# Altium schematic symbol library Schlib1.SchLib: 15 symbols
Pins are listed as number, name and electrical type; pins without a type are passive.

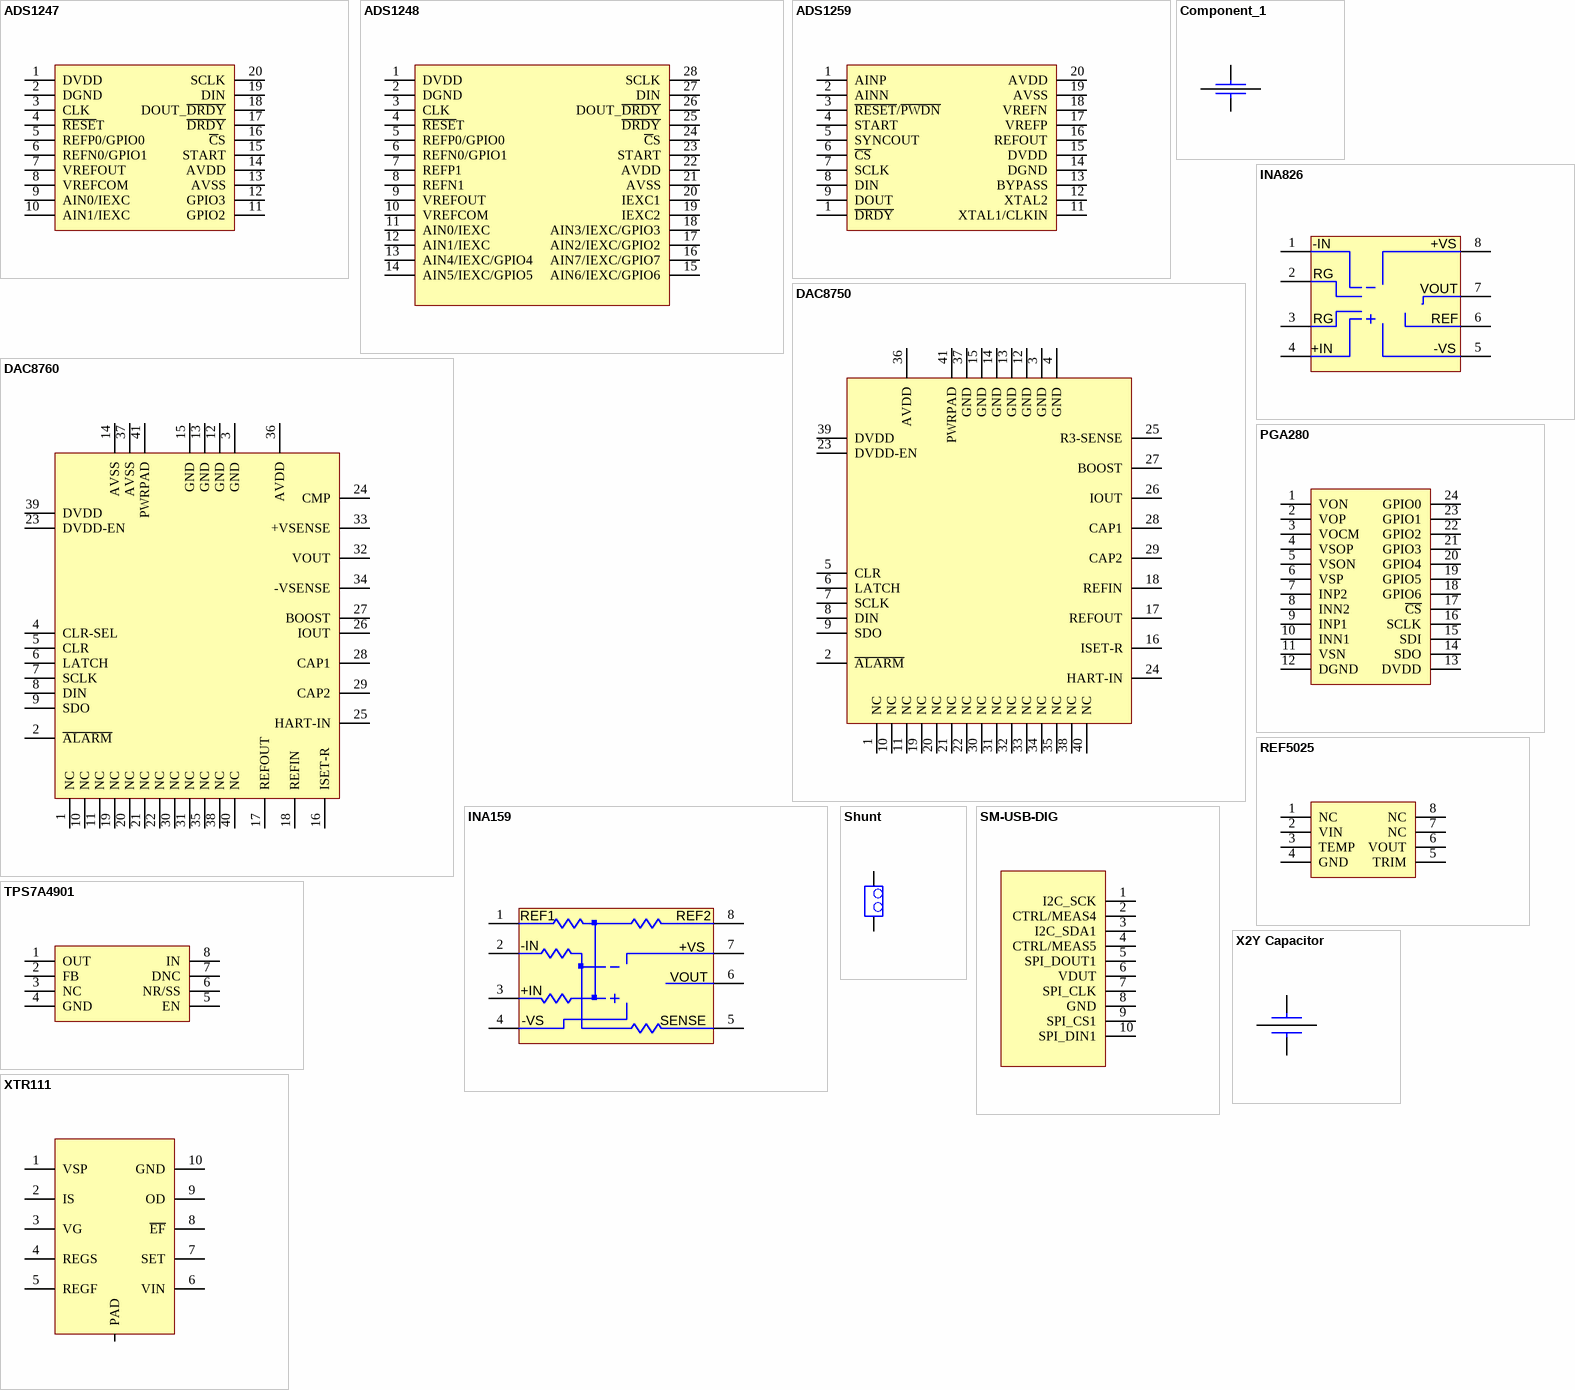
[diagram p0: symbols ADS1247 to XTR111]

## ADS1247
designator U?, comment Used in BOM report
SymbolVersion: use current date i.e. 2008-05-20; SymbolCreator: Use LDAP id; CompType: Used in some BOM reports.  Useful for finding later.; U/M: EA, IN, or GM
pins: 1 DVDD, 2 DGND, 3 CLK, 4 ~{RESE}T, 5 REFP0/GPIO0, 6 REFN0/GPIO1, 7 VREFOUT, 8 VREFCOM, 9 AIN0/IEXC, 10 AIN1/IEXC, 11 GPIO2, 12 GPIO3, 13 AVSS, 14 AVDD, 15 START, 16 ~{C}S, 17 ~{DRDY}, 18 DOUT_~{DRDY}, 19 DIN, 20 SCLK

## ADS1248
designator U?, comment Used in BOM report
SymbolVersion: use current date i.e. 2008-05-20; SymbolCreator: Use LDAP id; CompType: Used in some BOM reports.  Useful for finding later.; U/M: EA, IN, or GM
pins: 1 DVDD, 2 DGND, 3 CLK, 4 ~{RESE}T, 5 REFP0/GPIO0, 6 REFN0/GPIO1, 7 REFP1, 8 REFN1, 9 VREFOUT, 10 VREFCOM, 11 AIN0/IEXC, 12 AIN1/IEXC, 13 AIN4/IEXC/GPIO4, 14 AIN5/IEXC/GPIO5, 15 AIN6/IEXC/GPIO6, 16 AIN7/IEXC/GPIO7, 17 AIN2/IEXC/GPIO2, 18 AIN3/IEXC/GPIO3, 19 IEXC2, 20 IEXC1, 21 AVSS, 22 AVDD, 23 START, 24 ~{C}S, 25 ~{DRDY}, 26 DOUT_~{DRDY}, 27 DIN, 28 SCLK

## ADS1259
designator U?, comment Used in BOM report
SymbolVersion: use current date i.e. 2008-05-20; SymbolCreator: Use LDAP id; CompType: Used in some BOM reports.  Useful for finding later.; U/M: EA, IN, or GM
pins: 1 AINP, 1 ~{DRDY}, 2 AINN, 3 ~{RESET}/~{PWDN}, 4 START, 5 SYNCOUT, 6 ~{CS}, 7 SCLK, 8 DIN, 9 DOUT, 11 XTAL1/CLKIN, 12 XTAL2, 13 BYPASS, 14 DGND, 15 DVDD, 16 REFOUT, 17 VREFP, 18 VREFN, 19 AVSS, 20 AVDD

## Component_1
designator U?, comment Used in BOM report
SymbolVersion: use current date i.e. 2008-05-20; SymbolCreator: Use LDAP id; CompType: Used in some BOM reports.  Useful for finding later.; U/M: EA, IN, or GM
pins: 2, 2, 3, 4

## DAC8750
designator U?, comment Used in BOM report
SymbolVersion: use current date i.e. 2008-05-20; SymbolCreator: Use LDAP id; CompType: Used in some BOM reports.  Useful for finding later.; U/M: EA, IN, or GM
pins: 1 NC, 2 ~{ALARM}, 3 GND, 4 GND, 5 CLR, 6 LATCH, 7 SCLK, 8 DIN, 9 SDO, 10 NC, 11 NC, 12 GND, 13 GND, 14 GND, 15 GND, 16 ISET-R, 17 REFOUT, 18 REFIN, 19 NC, 20 NC, 21 NC, 22 NC, 23 DVDD-EN, 24 HART-IN, 25 R3-SENSE, 26 IOUT, 27 BOOST, 28 CAP1, 29 CAP2, 30 NC, 31 NC, 32 NC, 33 NC, 34 NC, 35 NC, 36 AVDD, 37 GND, 38 NC, 39 DVDD, 40 NC, 41 PWRPAD

## DAC8760
designator U?, comment Used in BOM report
SymbolVersion: use current date i.e. 2008-05-20; SymbolCreator: Use LDAP id; CompType: Used in some BOM reports.  Useful for finding later.; U/M: EA, IN, or GM
pins: 1 NC, 2 ~{ALARM}, 3 GND, 4 CLR-SEL, 5 CLR, 6 LATCH, 7 SCLK, 8 DIN, 9 SDO, 10 NC, 11 NC, 12 GND, 13 GND, 14 AVSS, 15 GND, 16 ISET-R, 17 REFOUT, 18 REFIN, 19 NC, 20 NC, 21 NC, 22 NC, 23 DVDD-EN, 24 CMP, 25 HART-IN, 26 IOUT, 27 BOOST, 28 CAP1, 29 CAP2, 30 NC, 31 NC, 32 VOUT, 33 +VSENSE, 34 -VSENSE, 35 NC, 36 AVDD, 37 AVSS, 38 NC, 39 DVDD, 40 NC, 41 PWRPAD

## INA159
designator U?, comment Used in BOM report
SymbolVersion: use current date i.e. 2008-05-20; SymbolCreator: Use LDAP id; CompType: Used in some BOM reports.  Useful for finding later.; U/M: EA, IN, or GM
pins: 1 REF1, 2 -IN, 3 +IN, 4 V-, 5 SENSE, 6 OUT, 7 VOUT, 8 REF2

## INA826
designator U?, comment Used in BOM report
SymbolVersion: use current date i.e. 2008-05-20; SymbolCreator: Use LDAP id; CompType: Used in some BOM reports.  Useful for finding later.; U/M: EA, IN, or GM
pins: 1 -IN, 2 RG, 3 RG, 4 +IN, 5 -VS, 6 REF, 7 VOUT, 8 +VS

## PGA280
designator U?, comment Used in BOM report
SymbolVersion: use current date i.e. 2008-05-20; SymbolCreator: Use LDAP id; CompType: Used in some BOM reports.  Useful for finding later.; U/M: EA, IN, or GM
pins: 1 VON, 2 VOP, 3 VOCM, 4 VSOP, 5 VSON, 6 VSP, 7 INP2, 8 INN2, 9 INP1, 10 INN1, 11 VSN, 12 DGND, 13 DVDD, 14 SDO, 15 SDI, 16 SCLK, 17 ~{CS}, 18 GPIO6, 19 GPIO5, 20 GPIO4, 21 GPIO3, 22 GPIO2, 23 GPIO1, 24 GPIO0

## REF5025
designator U?, comment Used in BOM report
SymbolVersion: use current date i.e. 2008-05-20; SymbolCreator: Use LDAP id; CompType: Used in some BOM reports.  Useful for finding later.; U/M: EA, IN, or GM
pins: 1 NC, 2 VIN, 3 TEMP, 4 GND, 5 TRIM, 6 VOUT, 7 NC, 8 NC

## Shunt
designator J?, comment Used in BOM report  (value not drawn)
SymbolVersion: use current date i.e. 2008-05-20; SymbolCreator: Use LDAP id; CompType: Used in some BOM reports.  Useful for finding later.; U/M: EA, IN, or GM
pins: 1, 2

## SM-USB-DIG
designator U?, comment Used in BOM report
SymbolVersion: use current date i.e. 2008-05-20; SymbolCreator: Use LDAP id; CompType: Used in some BOM reports.  Useful for finding later.; U/M: EA, IN, or GM
pins: 1 I2C_SCK, 2 CTRL/MEAS4, 3 I2C_SDA1, 4 CTRL/MEAS5, 5 SPI_DOUT1, 6 VDUT, 7 SPI_CLK, 8 GND, 9 SPI_CS1, 10 SPI_DIN1

## TPS7A4901
designator U?, comment Used in BOM report
SymbolVersion: use current date i.e. 2008-05-20; SymbolCreator: Use LDAP id; CompType: Used in some BOM reports.  Useful for finding later.; U/M: EA, IN, or GM
pins: 1 OUT, 2 FB, 3 NC, 4 GND, 5 EN, 6 NR/SS, 7 DNC, 8 IN

## X2Y Capacitor
designator U?, comment Used in BOM report
SymbolVersion: use current date i.e. 2008-05-20; SymbolCreator: Use LDAP id; CompType: Used in some BOM reports.  Useful for finding later.; U/M: EA, IN, or GM
pins: 1, 2, 3, 4

## XTR111
designator U?, comment Used in BOM report
SymbolVersion: use current date i.e. 2008-05-20; SymbolCreator: Use LDAP id; CompType: Used in some BOM reports.  Useful for finding later.; U/M: EA, IN, or GM
pins: 1 VSP, 2 IS, 3 VG, 4 REGS, 5 REGF, 6 VIN, 7 SET, 8 ~{EF}, 9 OD, 10 GND, 11 PAD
